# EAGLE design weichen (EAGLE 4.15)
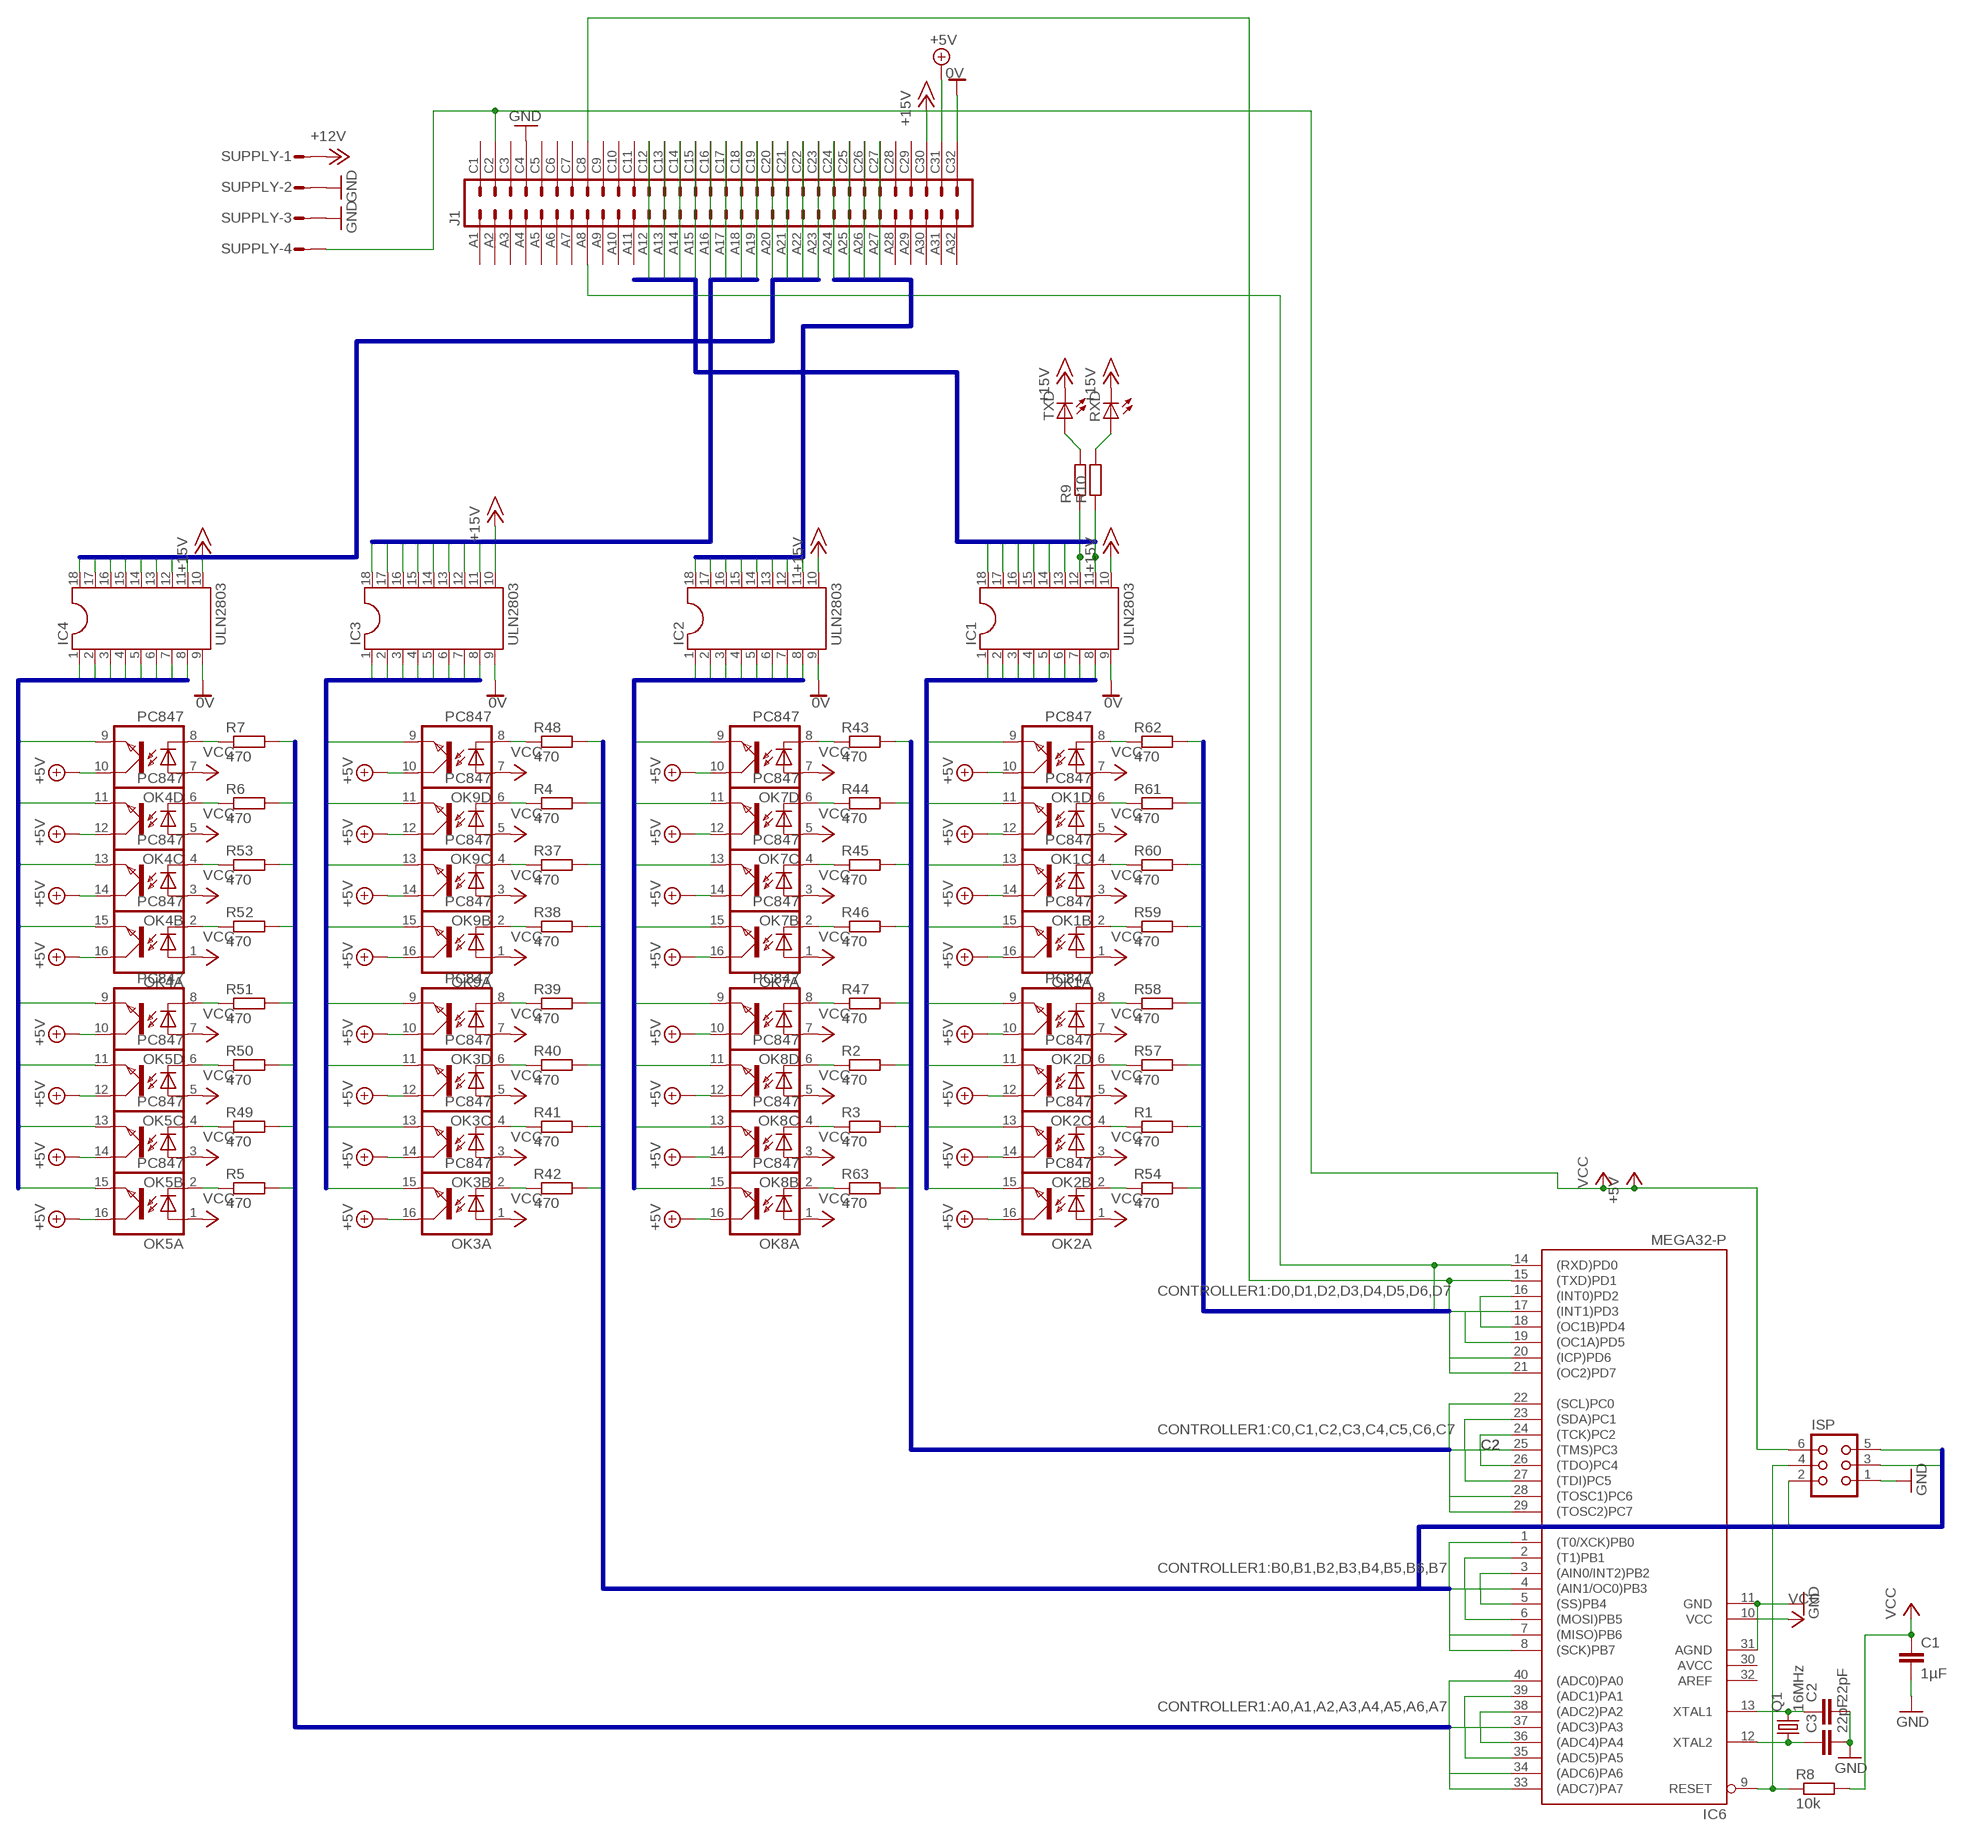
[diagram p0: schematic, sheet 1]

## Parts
C1  1µF  C-EU050-024X044  [C050-024X044]
C2  22pF  C-EU025-025X050  [C025-025X050]
C3  22pF  C-EU025-025X050  [C025-025X050]
IC1  ULN2803  DIL18  [DIL18]
IC2  ULN2803  DIL18  [DIL18]
IC3  ULN2803  DIL18  [DIL18]
IC4  ULN2803  DIL18  [DIL18]
IC6  MEGA32-P  [DIL40]
ISP  CON06L  [CON06L]
J1  VG64  [VG64]
OK1  PC847  [DIL16]
OK2  PC847  [DIL16]
OK3  PC847  [DIL16]
OK4  PC847  [DIL16]
OK5  PC847  [DIL16]
OK7  PC847  [DIL16]
OK8  PC847  [DIL16]
OK9  PC847  [DIL16]
Q1  16MHz  CRYSTALHC18U-V  [HC18U-V]
R1  470  R-EU_0204/7  [0204/7]
R2  470  R-EU_0204/7  [0204/7]
R3  470  R-EU_0204/7  [0204/7]
R4  470  R-EU_0204/7  [0204/7]
R5  470  R-EU_0204/7  [0204/7]
R6  470  R-EU_0204/7  [0204/7]
R7  470  R-EU_0204/7  [0204/7]
R8  10k  R-EU_0204/7  [0204/7]
R9  R-EU_0204/7  [0204/7]
R10  R-EU_0204/7  [0204/7]
R37  470  R-EU_0204/7  [0204/7]
R38  470  R-EU_0204/7  [0204/7]
R39  470  R-EU_0204/7  [0204/7]
R40  470  R-EU_0204/7  [0204/7]
R41  470  R-EU_0204/7  [0204/7]
R42  470  R-EU_0204/7  [0204/7]
R43  470  R-EU_0204/7  [0204/7]
R44  470  R-EU_0204/7  [0204/7]
R45  470  R-EU_0204/7  [0204/7]
R46  470  R-EU_0204/7  [0204/7]
R47  470  R-EU_0204/7  [0204/7]
R48  470  R-EU_0204/7  [0204/7]
R49  470  R-EU_0204/7  [0204/7]
R50  470  R-EU_0204/7  [0204/7]
R51  470  R-EU_0204/7  [0204/7]
R52  470  R-EU_0204/7  [0204/7]
R53  470  R-EU_0204/7  [0204/7]
R54  470  R-EU_0204/7  [0204/7]
R57  470  R-EU_0204/7  [0204/7]
R58  470  R-EU_0204/7  [0204/7]
R59  470  R-EU_0204/7  [0204/7]
R60  470  R-EU_0204/7  [0204/7]
R61  470  R-EU_0204/7  [0204/7]
R62  470  R-EU_0204/7  [0204/7]
R63  470  R-EU_0204/7  [0204/7]
RXD  LED5MM  [LED5MM]
SUPPLY  L04P  [L04P]
TXD  LED5MM  [LED5MM]

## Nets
0V: IC1.9 IC2.9 IC3.9 IC4.9 J1.C32
+5V: J1.C31 OK1.10(D:COL) OK1.12(C:COL) OK1.14(B:COL) OK1.16(A:COL) OK2.10(D:COL) OK2.12(C:COL) OK2.14(B:COL) OK2.16(A:COL) OK3.10(D:COL) OK3.12(C:COL) OK3.14(B:COL) OK3.16(A:COL) OK4.10(D:COL) OK4.12(C:COL) OK4.14(B:COL) OK4.16(A:COL) OK5.10(D:COL) OK5.12(C:COL) OK5.14(B:COL) OK5.16(A:COL) OK7.10(D:COL) OK7.12(C:COL) OK7.14(B:COL) OK7.16(A:COL) OK8.10(D:COL) OK8.12(C:COL) OK8.14(B:COL) OK8.16(A:COL) OK9.10(D:COL) OK9.12(C:COL) OK9.14(B:COL) OK9.16(A:COL)
+12V: SUPPLY.1
+15V: IC1.10 IC2.10 IC3.10 IC4.10 J1.C30 RXD.K(C) TXD.K(C)
A0: IC6.40((ADC0)PA0) R5.2
A1: IC6.39((ADC1)PA1) R49.2
A2: IC6.38((ADC2)PA2) R50.2
A3: IC6.37((ADC3)PA3) R51.2
A4: IC6.36((ADC4)PA4) R52.2
A5: IC6.35((ADC5)PA5) R53.2
A6: IC6.34((ADC6)PA6) R6.2
A7: IC6.33((ADC7)PA7) R7.2
AA0: IC4.18 J1.C20
AA1: IC4.17 J1.A20
AA2: IC4.16 J1.C21
AA3: IC4.15 J1.A21
AA4: IC4.14 J1.C22
AA5: IC4.13 J1.A22
AA6: IC4.12 J1.C23
AA7: IC4.11 J1.A23
AB0: IC3.18 J1.C16
AB1: IC3.17 J1.A16
AB2: IC3.16 J1.C17
AB3: IC3.15 J1.A17
AB4: IC3.14 J1.C18
AB5: IC3.13 J1.A18
AB6: IC3.12 J1.C19
AB7: IC3.11 J1.A19
AC0: IC2.18 J1.C24
AC1: IC2.17 J1.A24
AC2: IC2.16 J1.C25
AC3: IC2.15 J1.A25
AC4: IC2.14 J1.C26
AC5: IC2.13 J1.A26
AC6: IC2.12 J1.C27
AC7: IC2.11 J1.A27
AD0: IC1.18 J1.A12
AD1: IC1.17 J1.C12
AD2: IC1.16 J1.A13
AD3: IC1.15 J1.C13
AD4: IC1.14 J1.A14
AD5: IC1.13 J1.C14
AD6: IC1.12 J1.A15 R9.1
AD7: IC1.11 J1.C15 R10.1
B0: IC6.1((T0/XCK)PB0) R48.2
B1: IC6.2((T1)PB1) R4.2
B2: IC6.3((AIN0/INT2)PB2) R37.2
B3: IC6.4((AIN1/OC0)PB3) R38.2
B4: IC6.5((SS)PB4) R39.2
B5: IC6.6((MOSI)PB5) ISP.3 R40.2
B6: IC6.7((MISO)PB6) ISP.2 R41.2
B7: IC6.8((SCK)PB7) ISP.5 R42.2
C0: IC6.22((SCL)PC0) R43.2
C1: IC6.23((SDA)PC1) R44.2
C2: IC6.24((TCK)PC2) R45.2
C3: IC6.25((TMS)PC3) R46.2
C4: IC6.26((TDO)PC4) R47.2
C5: IC6.27((TDI)PC5) R2.2
C6: IC6.28((TOSC1)PC6) R3.2
C7: IC6.29((TOSC2)PC7) R63.2
D0: IC6.14((RXD)PD0) J1.A8 R62.2
D1: IC6.15((TXD)PD1) J1.C8 R61.2
D2: IC6.16((INT0)PD2) R60.2
D3: IC6.17((INT1)PD3) R59.2
D4: IC6.18((OC1B)PD4) R58.2
D5: IC6.19((OC1A)PD5) R57.2
D6: IC6.20((ICP)PD6) R1.2
D7: IC6.21((OC2)PD7) R54.2
GND: C1.2 C2.2 C3.2 IC6.11(GND) IC6.31(AGND) ISP.1 J1.C4 SUPPLY.2 SUPPLY.3
N$1: OK5.2(A:C) R5.1
N$2: IC6.9(RESET) ISP.4 R8.1
N$3: R10.2 RXD.A
N$4: R9.2 TXD.A
N$5: OK4.6(C:C) R6.1
N$6: OK4.8(D:C) R7.1
N$7: OK5.4(B:C) R49.1
N$8: OK5.6(C:C) R50.1
N$10: OK5.8(D:C) R51.1
N$11: OK4.2(A:C) R52.1
N$12: OK4.4(B:C) R53.1
N$13: OK9.6(C:C) R4.1
N$14: OK9.4(B:C) R37.1
N$15: OK9.2(A:C) R38.1
N$16: OK3.8(D:C) R39.1
N$17: OK3.6(C:C) R40.1
N$18: OK3.4(B:C) R41.1
N$19: OK3.2(A:C) R42.1
N$20: OK9.8(D:C) R48.1
N$21: OK8.6(C:C) R2.1
N$22: OK8.4(B:C) R3.1
N$23: OK7.8(D:C) R43.1
N$24: OK7.6(C:C) R44.1
N$25: OK7.4(B:C) R45.1
N$26: OK7.2(A:C) R46.1
N$27: OK8.8(D:C) R47.1
N$28: OK8.2(A:C) R63.1
N$29: OK2.4(B:C) R1.1
N$30: OK2.2(A:C) R54.1
N$31: OK2.6(C:C) R57.1
N$32: OK2.8(D:C) R58.1
N$33: OK1.2(A:C) R59.1
N$34: OK1.4(B:C) R60.1
N$35: OK1.6(C:C) R61.1
N$36: OK1.8(D:C) R62.1
N$41: C2.1 IC6.13(XTAL1) Q1.2
N$42: C3.1 IC6.12(XTAL2) Q1.1
OA0: IC4.8 OK4.9(D:EMIT)
OA1: IC4.7 OK4.11(C:EMIT)
OA2: IC4.6 OK4.13(B:EMIT)
OA3: IC4.5 OK4.15(A:EMIT)
OA4: IC4.4 OK5.9(D:EMIT)
OA5: IC4.3 OK5.11(C:EMIT)
OA6: IC4.2 OK5.13(B:EMIT)
OA7: IC4.1 OK5.15(A:EMIT)
OB0: IC3.8 OK9.9(D:EMIT)
OB1: IC3.7 OK9.11(C:EMIT)
OB2: IC3.6 OK9.13(B:EMIT)
OB3: IC3.5 OK9.15(A:EMIT)
OB4: IC3.4 OK3.9(D:EMIT)
OB5: IC3.3 OK3.11(C:EMIT)
OB6: IC3.2 OK3.13(B:EMIT)
OB7: IC3.1 OK3.15(A:EMIT)
OC0: IC2.8 OK7.9(D:EMIT)
OC1: IC2.7 OK7.11(C:EMIT)
OC2: IC2.6 OK7.13(B:EMIT)
OC3: IC2.5 OK7.15(A:EMIT)
OC4: IC2.4 OK8.9(D:EMIT)
OC5: IC2.3 OK8.11(C:EMIT)
OC6: IC2.2 OK8.13(B:EMIT)
OC7: IC2.1 OK8.15(A:EMIT)
OD0: IC1.8 OK1.9(D:EMIT)
OD1: IC1.7 OK1.11(C:EMIT)
OD2: IC1.6 OK1.13(B:EMIT)
OD3: IC1.5 OK1.15(A:EMIT)
OD4: IC1.4 OK2.9(D:EMIT)
OD5: IC1.3 OK2.11(C:EMIT)
OD6: IC1.2 OK2.13(B:EMIT)
OD7: IC1.1 OK2.15(A:EMIT)
VCC: C1.1 IC6.10(VCC) ISP.6 J1.C2 OK1.1(A:A) OK1.3(B:A) OK1.5(C:A) OK1.7(D:A) OK2.1(A:A) OK2.3(B:A) OK2.5(C:A) OK2.7(D:A) OK3.1(A:A) OK3.3(B:A) OK3.5(C:A) OK3.7(D:A) OK4.1(A:A) OK4.3(B:A) OK4.5(C:A) OK4.7(D:A) OK5.1(A:A) OK5.3(B:A) OK5.5(C:A) OK5.7(D:A) OK7.1(A:A) OK7.3(B:A) OK7.5(C:A) OK7.7(D:A) OK8.1(A:A) OK8.3(B:A) OK8.5(C:A) OK8.7(D:A) OK9.1(A:A) OK9.3(B:A) OK9.5(C:A) OK9.7(D:A) R8.2 SUPPLY.4 ; supply symbol labelled +5V
Unconnected: J1.A1 J1.A2 J1.A3 J1.A4 J1.A5 J1.A6 J1.A7 J1.A9 J1.A10 J1.A11 J1.A28 J1.A29 J1.A30 J1.A31 J1.A32 J1.C1 J1.C3 J1.C5 J1.C6 J1.C7 J1.C9 J1.C10 J1.C11 J1.C28 J1.C29

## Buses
CONTROLLER1:A0,A1,A2,A3,A4,A5,A6,A7
CONTROLLER1:B0,B1,B2,B3,B4,B5,B6,B7
CONTROLLER1:C0,C1,C2,C3,C4,C5,C6,C7
CONTROLLER1:D0,D1,D2,D3,D4,D5,D6,D7
OPTOKOPPLER1:OD0,OD1,OD2,OD3,OD4,OD5,OD6,OD7
OPTOKOPPLER1:OC0,OC1,OC2,OC3,OC4,OC5,OC6,OC7
OPTOKOPPLER1:OB0,OB1,OB2,OB3,OB4,OB5,OB6,OB7
OPTOKOPPLER1:OA0,OA1,OA2,OA3,OA4,OA5,OA6,OA7
AUSGANG:AD0,AD1,AD2,AD3,AD4,AD5,AD6,AD7
AUSGANG:AC0,AC1,AC2,AC3,AC4,AC5,AC6,AC7
AUSGANG:AA0,AA1,AA2,AA3,AA4,AA5,AA6,AA7
AUSGANG:AB0,AB1,AB2,AB3,AB4,AB5,AB6,AB7

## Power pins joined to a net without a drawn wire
AREF: IC6.32(AREF)
AVCC: IC6.30(AVCC)

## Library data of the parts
C1-C3 = rcl:C-EU: CAPACITOR, European symbol
IC1-IC4 = ic-package:DIL18: Dual In Line
IC6 = atmel:MEGA32-P: MICROCONTROLLER 32 Kbytes FLASH 2 Kbytes SRAM 1 Kbytes EEPROM USART 8-channel 10 bit ADC Source: www.atmel.com .. doc2503.pdf
ISP = con-harting:CON06L: CONNECTOR
J1 = 19inch:VG64: PCB EUROCARD, 64-pin type C/AC, 2.54 mm
OK1-OK5 OK7-OK9 = optocoupler:PC847: SHARP OPTO COUPLER
Q1 = crystal:CRYSTAL: CRYSTAL
R1-R10 R37-R54 R57-R63 = rcl:R-EU_: RESISTOR, European symbol
RXD TXD = led:LED: LED
SUPPLY = con-amp-mt:L04P: AMP MT CONNECTOR

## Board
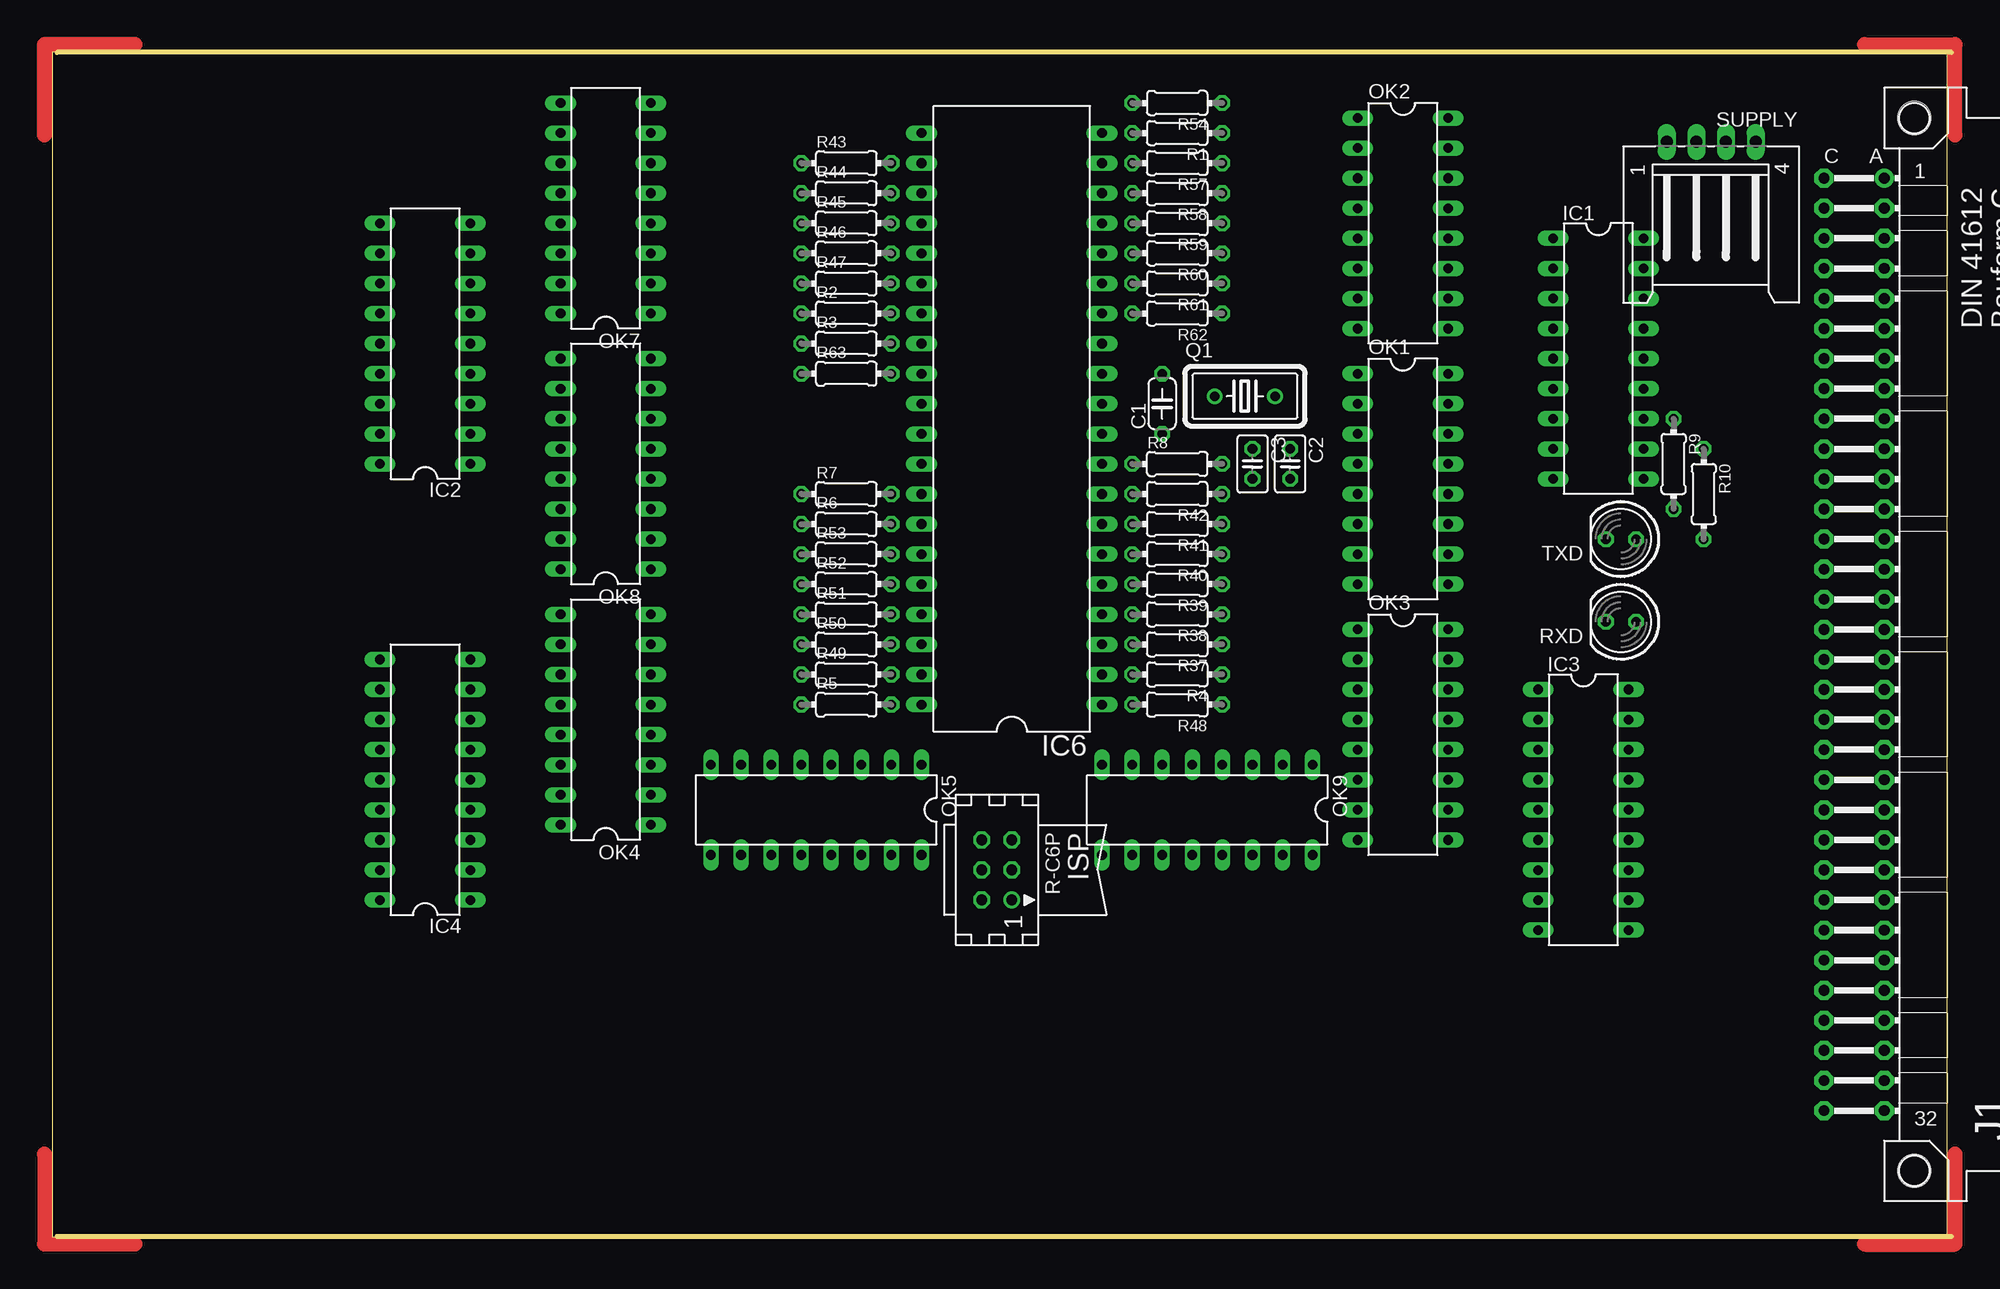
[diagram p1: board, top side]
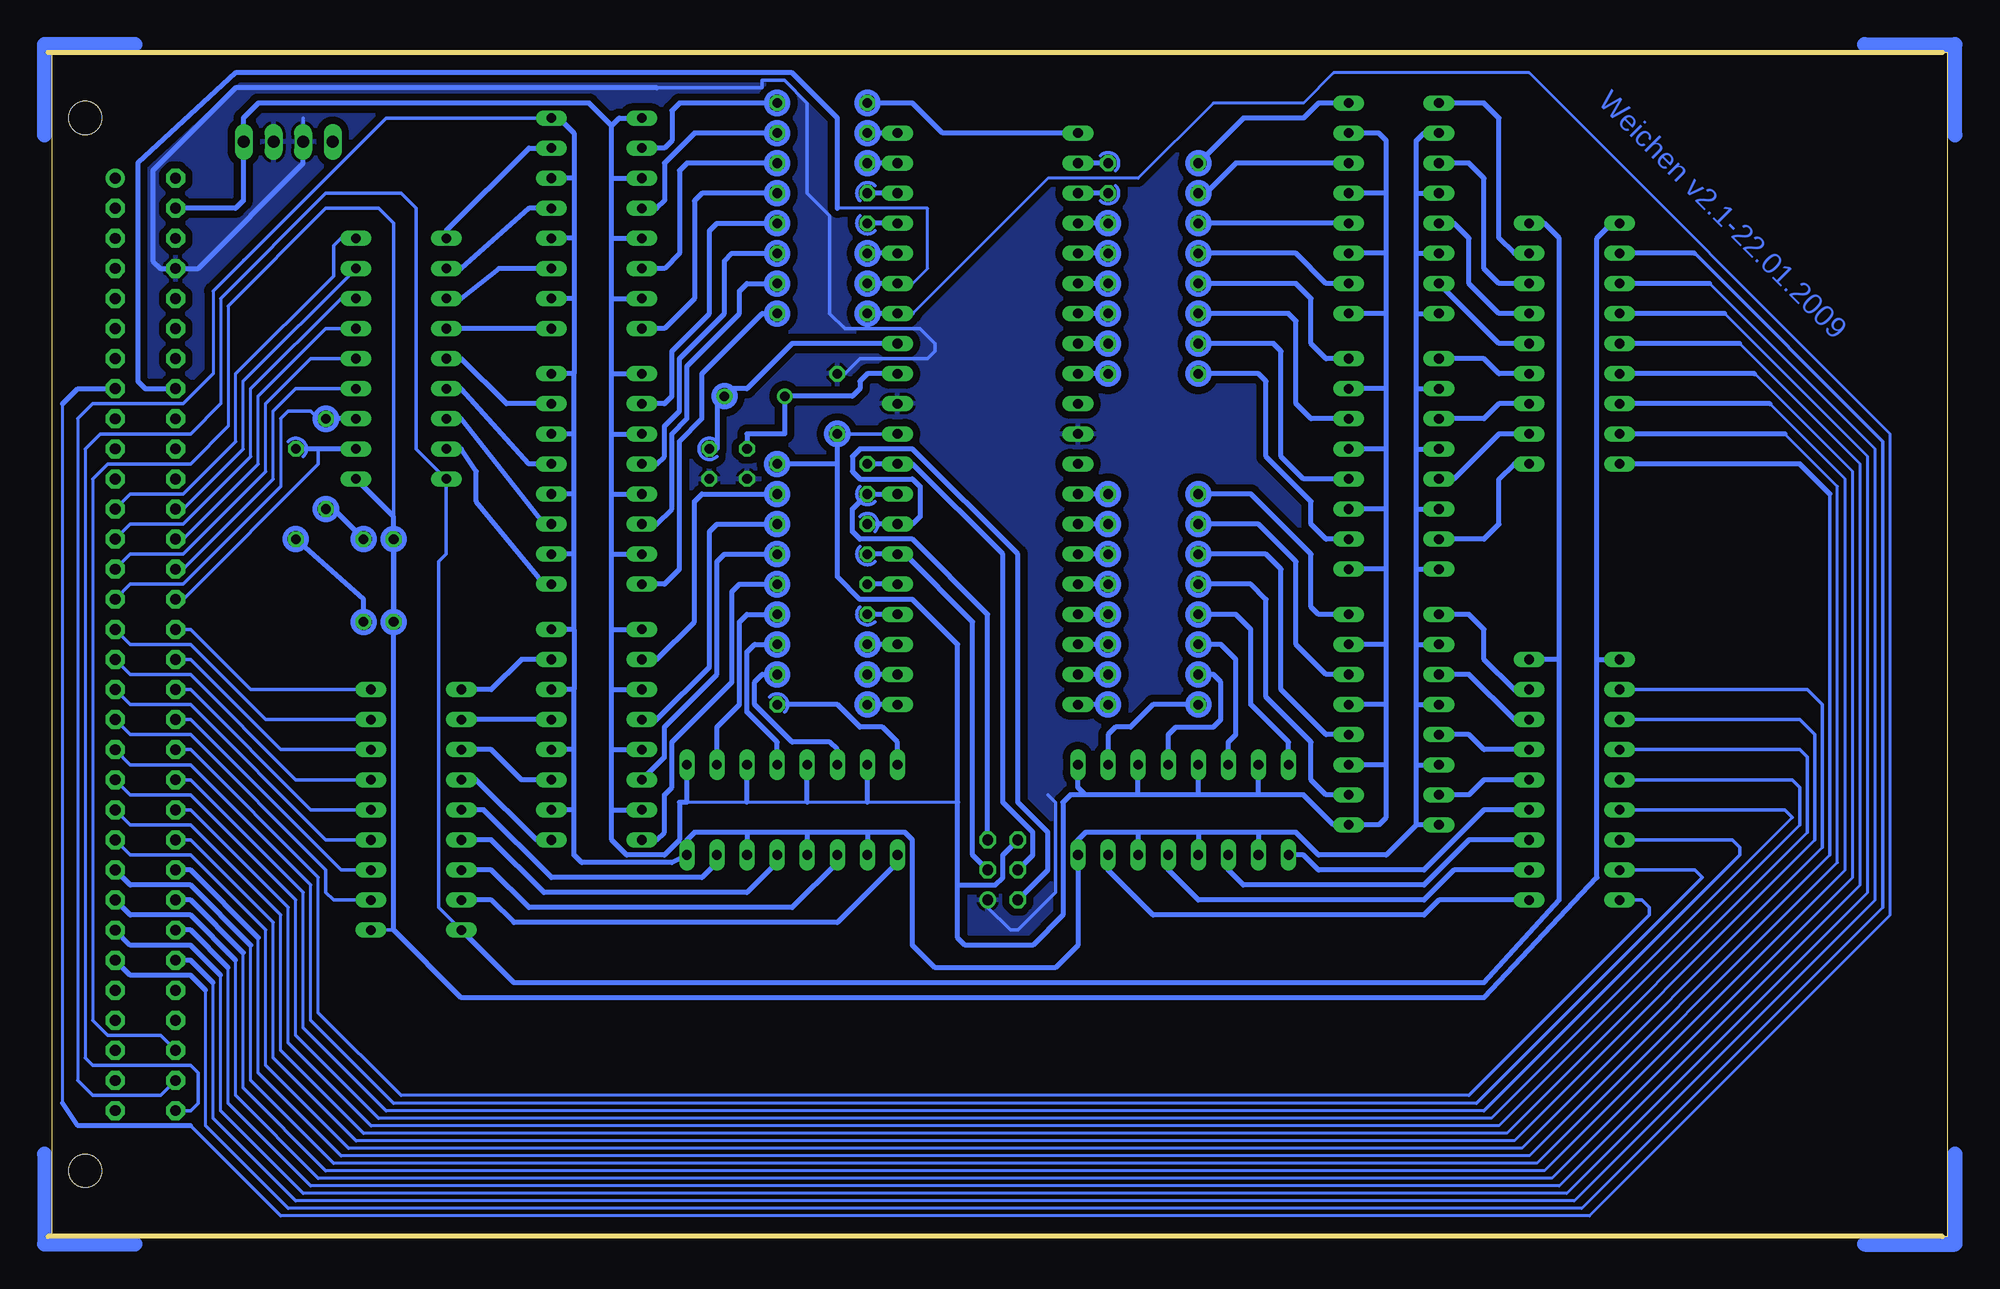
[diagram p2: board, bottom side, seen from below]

Size 160.39 x 100.03 mm. Coordinates in mm from the lower left corner, seen from the top.
Outline: 0.39,0.01 160.39,0.01
Outline: 160.39,100.01 0.39,100.01
Copper layers (1*16): Top 0.035mm / dielectric 1.5mm / Bottom 0.035mm
Design rules "default": minimum track width 10mil, minimum drill 24mil, track to track 8mil, track to pad 8mil, pad to pad 8mil, via to via 8mil, smd to smd 8mil, copper to edge 40mil, drill to drill 8mil, minimum pad ring 10mil, minimum via ring 8mil, stop-mask expansion 4mil, vias tented up to drill 0mil, thermal gap 10mil

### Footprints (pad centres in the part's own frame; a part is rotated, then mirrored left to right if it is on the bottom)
C050-024X044 = drill 0.813 octagon: 1 -2.54,0; 2 2.54,0
C025-025X050 = drill 0.813 octagon: 1 -1.27,0; 2 1.27,0
DIL18 = drill 0.813 long: 1 -10.16,-3.81; 2 -7.62,-3.81; 3 -5.08,-3.81; 4 -2.54,-3.81; 5 0,-3.81; 6 2.54,-3.81; 7 5.08,-3.81; 8 7.62,-3.81; 9 10.16,-3.81; 10 10.16,3.81; 11 7.62,3.81; 12 5.08,3.81; 13 2.54,3.81; 14 0,3.81; 15 -2.54,3.81; 16 -5.08,3.81; 17 -7.62,3.81; 18 -10.16,3.81
DIL40 = drill 0.813 long: 1 -24.13,-7.62; 2 -21.59,-7.62; 3 -19.05,-7.62; 4 -16.51,-7.62; 5 -13.97,-7.62; 6 -11.43,-7.62; 7 -8.89,-7.62; 8 -6.35,-7.62; 9 -3.81,-7.62; 10 -1.27,-7.62; 11 1.27,-7.62; 12 3.81,-7.62; 13 6.35,-7.62; 14 8.89,-7.62; 15 11.43,-7.62; 16 13.97,-7.62; 17 16.51,-7.62; 18 19.05,-7.62; 19 21.59,-7.62; 20 24.13,-7.62; 21 24.13,7.62; 22 21.59,7.62; 23 19.05,7.62; 24 16.51,7.62; 25 13.97,7.62; 26 11.43,7.62; 27 8.89,7.62; 28 6.35,7.62; 29 3.81,7.62; 30 1.27,7.62; 31 -1.27,7.62; 32 -3.81,7.62; 33 -6.35,7.62; 34 -8.89,7.62; 35 -11.43,7.62; 36 -13.97,7.62; 37 -16.51,7.62; 38 -19.05,7.62; 39 -21.59,7.62; 40 -24.13,7.62
CON06L = drill 0.914 round: 1 2.54,1.27 | drill 0.914 octagon: 2 2.54,-1.27; 3 0,1.27; 4 0,-1.27; 5 -2.54,1.27; 6 -2.54,-1.27
VG64 = drill 0.914 pad 1.6 round: A1 154.94,39.37 | drill 0.914 pad 1.6 octagon: A2 154.94,36.83; A3 154.94,34.29; A4 154.94,31.75; A5 154.94,29.21; A6 154.94,26.67; A7 154.94,24.13; A8 154.94,21.59; A9 154.94,19.05; A10 154.94,16.51; A11 154.94,13.97; A12 154.94,11.43; A13 154.94,8.89; A14 154.94,6.35; A15 154.94,3.81; A16 154.94,1.27; A17 154.94,-1.27; A18 154.94,-3.81; A19 154.94,-6.35; A20 154.94,-8.89; A21 154.94,-11.43; A22 154.94,-13.97; A23 154.94,-16.51; A24 154.94,-19.05; A25 154.94,-21.59; A26 154.94,-24.13; A27 154.94,-26.67; A28 154.94,-29.21; A29 154.94,-31.75; A30 154.94,-34.29; A31 154.94,-36.83; A32 154.94,-39.37; C1 149.86,39.37; C2 149.86,36.83; C3 149.86,34.29; C4 149.86,31.75; C5 149.86,29.21; C6 149.86,26.67; C7 149.86,24.13; C8 149.86,21.59; C9 149.86,19.05; C10 149.86,16.51; C11 149.86,13.97; C12 149.86,11.43; C13 149.86,8.89; C14 149.86,6.35; C15 149.86,3.81; C16 149.86,1.27; C17 149.86,-1.27; C18 149.86,-3.81; C19 149.86,-6.35; C20 149.86,-8.89; C21 149.86,-11.43; C22 149.86,-13.97; C23 149.86,-16.51; C24 149.86,-19.05; C25 149.86,-21.59; C26 149.86,-24.13; C27 149.86,-26.67; C28 149.86,-29.21; C29 149.86,-31.75; C30 149.86,-34.29; C31 149.86,-36.83; C32 149.86,-39.37 | hole 2.794: 157.48,44.45; 157.48,-44.45
DIL16 = drill 0.813 long: 1 -8.89,-3.81; 2 -6.35,-3.81; 3 -3.81,-3.81; 4 -1.27,-3.81; 5 1.27,-3.81; 6 3.81,-3.81; 7 6.35,-3.81; 8 8.89,-3.81; 9 8.89,3.81; 10 6.35,3.81; 11 3.81,3.81; 12 1.27,3.81; 13 -1.27,3.81; 14 -3.81,3.81; 15 -6.35,3.81; 16 -8.89,3.81
HC18U-V = drill 0.813 round: 1 -2.54,0; 2 2.54,0
0204/7 = drill 0.813 octagon: 1 -3.81,0; 2 3.81,0
LED5MM = drill 0.813 octagon: A -1.27,0; K 1.27,0
L04P = drill 1.016 long: 1 3.75,-6.25; 2 1.25,-6.25; 3 -1.25,-6.25; 4 -3.75,-6.25

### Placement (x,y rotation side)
C1  93.73,70.33 90 top
C2  104.52,65.25 270 top
C3  101.35,65.25 270 top
IC1  130.56,74.14 270 top
IC2  31.5,75.41 90 top
IC3  129.29,36.04 270 top
IC4  31.5,38.58 90 top
IC6  81.03,69.06 90 top
ISP  79.76,30.96 270 top
J1  -0.25,50.01 0 top
OK1  114.05,63.98 270 top
OK2  114.05,85.57 270 top
OK3  114.05,42.39 270 top
OK4  46.74,43.66 90 top
OK5  64.52,36.04 180 top
OK7  46.74,86.84 90 top
OK8  46.74,65.25 90 top
OK9  97.54,36.04 180 top
Q1  100.71,70.97 0 top
R1  95,93.19 180 top
R2  67.06,77.95 0 top
R3  67.06,75.41 0 top
R4  95,47.47 180 top
R5  67.06,44.93 0 top
R6  67.06,60.17 0 top
R7  67.06,62.71 0 top
R8  95,65.25 0 top
R9  136.91,65.25 270 top
R10  139.45,62.71 270 top
R37  95,50.01 180 top
R38  95,52.55 180 top
R39  95,55.09 180 top
R40  95,57.63 180 top
R41  95,60.17 180 top
R42  95,62.71 180 top
R43  67.06,90.65 0 top
R44  67.06,88.11 0 top
R45  67.06,85.57 0 top
R46  67.06,83.03 0 top
R47  67.06,80.49 0 top
R48  95,44.93 180 top
R49  67.06,47.47 0 top
R50  67.06,50.01 0 top
R51  67.06,52.55 0 top
R52  67.06,55.09 0 top
R53  67.06,57.63 0 top
R54  95,95.73 180 top
R57  95,90.65 180 top
R58  95,88.11 180 top
R59  95,85.57 180 top
R60  95,83.03 180 top
R61  95,80.49 180 top
R62  95,77.95 180 top
R63  67.06,72.87 0 top
RXD  132.46,51.92 180 top
SUPPLY  140.08,86.21 180 top
TXD  132.46,58.9 180 top

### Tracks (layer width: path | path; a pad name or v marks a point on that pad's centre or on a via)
0V
  Bottom 0.254: 145.8,79.22 145.8,70.33 | 157.23,66.52 157.23,15.09
  Bottom 0.305: IC3.9 127.38,27.79 127.38,57 126.75,57.63 IC1.9 129.29,66.52 129.29,86.84 130.56,88.11 136.91,88.11 145.8,79.22 | 145.8,70.33 148.34,67.79 155.96,67.79 157.23,66.52 | 157.23,15.09 156.59,14.45 148.34,14.45 147.7,13.82 147.7,11.28 148.34,10.64 J1.C32
  Bottom 0.406: 32.77,48.74 32.77,84.3 34.04,85.57 IC2.9 | 32.77,48.74 IC4.9 | 32.77,48.74 32.77,28.42 39.12,21.44 121.03,21.44 IC3.9
+5V
  Bottom 0.254: 146.43,79.86 146.43,72.87 | 157.86,69.06 157.86,13.18
  Bottom 0.305: 115.95,36.04 115.95,51.28 115.95,93.19 | 117.22,94.46 118.49,94.46 131.83,94.46 143.89,82.4 | 143.89,82.4 146.43,79.86 | 146.43,72.87 148.97,70.33 156.59,70.33 157.86,69.06 | 157.86,13.18 156.59,11.91 150.88,11.91 J1.C31 | 143.89,82.4 143.83,82.46
  Bottom 0.406: 101.35,34.14 OK9.14 | 96.27,34.14 101.35,34.14 | 96.27,34.14 OK9.12 | 91.19,34.14 96.27,34.14 | 115.95,36.04 OK3.10 | 115.95,89.38 115.95,84.3 | 115.95,84.3 OK2.12 | 115.95,84.3 115.95,79.22 | 115.95,79.22 OK2.10 | 115.95,79.22 115.95,72.87 | 115.95,72.87 OK1.16 | 115.95,67.79 115.95,72.87 | 115.95,67.79 OK1.14 | 115.95,62.71 115.95,67.79 | 115.95,62.71 OK1.12 | 115.95,57.63 115.95,62.71 | 115.95,51.28 115.95,46.2 | 115.95,46.2 OK3.14 | 115.95,41.12 115.95,46.2 | 115.95,41.12 OK3.12 | 115.95,36.04 115.95,41.12 | 115.95,89.38 OK2.14 | 115.95,89.38 115.95,93.19 117.22,94.46 OK2.16 118.49,94.46 | 68.33,34.14 72.77,34.14 73.41,33.5 OK5.16 73.41,24.61 75.31,22.71 85.47,22.71 87.38,24.61 87.38,33.5 88.01,34.14 91.19,34.14 | 68.33,34.14 OK5.14 | 63.25,34.14 68.33,34.14 | 63.25,34.14 OK5.12 | 58.17,34.14 63.25,34.14 | 44.83,34.77 47.37,32.23 53.09,32.23 54.99,34.14 58.17,34.14 | OK4.16 44.83,34.77 | 44.83,34.77 44.83,39.85 | 44.83,39.85 OK4.14 | 44.83,39.85 44.83,44.93 | 44.83,44.93 OK4.12 | 44.83,44.93 44.83,50.01 | 44.83,50.01 OK4.10 | 44.83,50.01 44.83,56.36 | 44.83,56.36 OK8.16 | 44.83,56.36 44.83,61.44 | 44.83,61.44 OK8.14 | 44.83,61.44 44.83,66.52 | 44.83,66.52 OK8.12 | 44.83,66.52 44.83,71.6 | 44.83,71.6 OK8.10 | 44.83,71.6 44.83,77.95 | 44.83,77.95 OK7.16 | 44.83,77.95 44.83,83.03 | 44.83,83.03 OK7.14 | 44.83,83.03 44.83,88.11 | 44.83,88.11 OK7.12 | 44.83,88.11 44.83,92.56 44.2,93.19 OK7.10 | 58.17,34.14 OK5.10 | 91.19,34.14 OK9.10 | 101.35,34.14 105.79,34.14 106.43,33.5 OK9.16 107.7,31.6 115.32,31.6 115.95,32.23 115.95,36.04 | 115.95,57.63 OK1.10 | 115.95,51.28 115.95,57.63 | 115.95,51.28 OK3.16
+15V
  Bottom 0.254: 145.16,78.59 145.16,68.43 | 156.59,63.98 156.59,18.26
  Bottom 0.305: TXD.K 131.19,85.57 132.46,86.84 136.91,86.84 145.16,78.59 | 145.16,68.43 148.34,65.25 155.32,65.25 156.59,63.98 | 156.59,18.26 155.32,16.99 150.88,16.99 J1.C30 | 131.19,25.88 IC3.10
  Bottom 0.406: IC1.10 131.19,60.81 TXD.K | 29.59,48.74 IC4.10 | IC2.10 28.32,85.57 29.59,84.3 29.59,48.74 | 29.59,48.74 29.59,30.33 39.12,20.17 125.48,20.17 131.19,25.88 TXD.K | TXD.K RXD.K
A0
  Bottom 0.406: R5.2 IC6.40
A1
  Bottom 0.406: R49.2 IC6.39
A2
  Bottom 0.406: R50.2 IC6.38
A3
  Bottom 0.406: R51.2 IC6.37
A4
  Bottom 0.406: R52.2 IC6.36
A5
  Bottom 0.406: R53.2 IC6.35
A6
  Bottom 0.406: R6.2 IC6.34
A7
  Bottom 0.406: R7.2 IC6.33
AA0
  Bottom 0.254: 40.39,11.91 130.56,11.91 | 137.54,18.9 137.54,30.33
  Bottom 0.305: IC4.18 25.78,28.42 25.15,27.79 25.15,27.15 40.39,11.91 | 130.56,11.91 137.54,18.9 | J1.C20 148.34,41.12 137.54,30.33
AA1
  Bottom 0.254: 39.75,11.28 131.19,11.28 | 138.18,18.26 138.18,29.69
  Bottom 0.305: IC4.17 21.34,30.96 20.7,30.33 39.75,11.28 | 131.19,11.28 138.18,18.26 | 138.18,29.69 148.34,39.85 153.42,39.85 J1.A20
AA2
  Bottom 0.254: 39.12,10.64 131.83,10.64 | 138.81,17.63 138.81,29.06
  Bottom 0.305: IC4.16 18.16,33.5 17.53,32.87 17.53,32.23 39.12,10.64 | 131.83,10.64 138.81,17.63 | 138.81,29.06 148.34,38.58 J1.C21
AA3
  Bottom 0.254: 13.08,35.41 38.48,10.01 132.46,10.01 | 139.45,16.99 139.45,28.42
  Bottom 0.305: IC4.15 13.72,36.04 13.08,35.41 | 132.46,10.01 139.45,16.99 | 139.45,28.42 148.34,37.31 153.42,37.31 J1.A21
AA4
  Bottom 0.254: 12.45,34.77 37.85,9.37 133.1,9.37 | 140.08,16.36 140.08,27.79
  Bottom 0.305: IC4.14 13.08,38.58 12.45,37.95 12.45,34.77 | 133.1,9.37 140.08,16.36 | 140.08,27.79 148.34,36.04 J1.C22
AA5
  Bottom 0.254: 11.81,34.14 37.21,8.74 133.73,8.74 | 140.72,15.72 140.72,27.15
  Bottom 0.305: 27.05,41.12 12.45,41.12 11.81,40.49 11.81,34.14 | 133.73,8.74 140.72,15.72 | 140.72,27.15 148.34,34.77 153.42,34.77 J1.A22
  Bottom 0.406: 27.05,41.12 IC4.13
AA6
  Bottom 0.254: 11.18,33.5 36.58,8.1 134.37,8.1 | 141.35,15.09 141.35,26.52
  Bottom 0.305: IC4.12 12.45,43.66 11.18,42.39 11.18,33.5 | 134.37,8.1 141.35,15.09 | 141.35,26.52 148.34,33.5 J1.C23
AA7
  Bottom 0.254: 10.54,32.87 35.94,7.47 135,7.47 | 141.99,14.45 141.99,25.88
  Bottom 0.305: 27.05,46.2 11.81,46.2 10.54,44.93 10.54,32.87 | 135,7.47 141.99,14.45 | 141.99,25.88 148.34,32.23 153.42,32.23 J1.A23
  Bottom 0.406: 27.05,46.2 IC4.11
AB0
  Bottom 0.305: IC3.18 143.26,46.2 148.34,51.28 J1.C16
AB1
  Bottom 0.305: IC3.17 141.99,43.66 148.34,50.01 153.42,50.01 J1.A16
AB2
  Bottom 0.305: IC3.16 140.72,41.12 148.34,48.74 J1.C17
AB3
  Bottom 0.305: IC3.15 139.45,38.58 148.34,47.47 153.42,47.47 J1.A17
AB4
  Bottom 0.305: IC3.14 138.18,36.04 148.34,46.2 J1.C18
AB5
  Bottom 0.305: IC3.13 136.91,33.5 148.34,44.93 153.42,44.93 J1.A18
AB6
  Bottom 0.305: IC3.12 135.64,30.96 148.34,43.66 J1.C19
AB7
  Bottom 0.305: IC3.11 136.27,28.42 136.91,29.06 136.91,30.96 148.34,42.39 153.42,42.39 J1.A19
AC0
  Bottom 0.254: 9.91,32.23 35.31,6.83 135.64,6.83 | 142.62,13.82 142.62,25.25
  Bottom 0.305: 9.91,32.23 9.91,62.71 | 135.64,6.83 142.62,13.82
  Bottom 0.406: IC2.18 12.45,65.25 9.91,62.71 | 142.62,25.25 148.34,30.96 J1.C24
AC1
  Bottom 0.254: 13.72,67.79 9.27,63.35 9.27,31.6 34.67,6.2 136.27,6.2 | 143.26,13.18 143.26,24.61
  Bottom 0.305: 136.27,6.2 143.26,13.18
  Bottom 0.406: 13.72,67.79 IC2.17 | 143.26,24.61 148.34,29.69 153.42,29.69 J1.A24
AC2
  Bottom 0.254: 14.99,70.33 8.64,63.98 8.64,30.96 34.04,5.56 136.91,5.56 | 143.89,12.55 143.89,23.98
  Bottom 0.305: 136.91,5.56 143.89,12.55
  Bottom 0.406: 14.99,70.33 IC2.16 | 143.89,23.98 148.34,28.42 J1.C25
AC3
  Bottom 0.254: 16.26,72.87 8,64.62 8,30.33 33.4,4.93 137.54,4.93 | 144.53,11.91 144.53,23.34
  Bottom 0.305: 137.54,4.93 144.53,11.91
  Bottom 0.406: 16.26,72.87 IC2.15 | 144.53,23.34 148.34,27.15 153.42,27.15 J1.A25
AC4
  Bottom 0.254: 17.53,75.41 7.37,65.25 7.37,29.69 32.77,4.29 138.18,4.29 | 145.16,11.28 145.16,22.71
  Bottom 0.305: 138.18,4.29 145.16,11.28
  Bottom 0.406: 17.53,75.41 IC2.14 | 145.16,22.71 148.34,25.88 J1.C26
AC5
  Bottom 0.254: 18.8,77.95 6.73,65.89 6.73,29.06 32.13,3.66 138.81,3.66 | 145.8,10.64 145.8,22.07
  Bottom 0.305: 138.81,3.66 145.8,10.64
  Bottom 0.406: 18.8,77.95 IC2.13 | 145.8,22.07 148.34,24.61 153.42,24.61 J1.A26
AC6
  Bottom 0.254: 20.07,80.49 6.1,66.52 6.1,28.42 31.5,3.02 139.45,3.02 | 146.43,10.01 146.43,21.44
  Bottom 0.305: 139.45,3.02 146.43,10.01
  Bottom 0.406: 20.07,80.49 IC2.12 | 146.43,21.44 148.34,23.34 J1.C27
AC7
  Bottom 0.254: 5.46,27.79 30.86,2.39 140.08,2.39 | 147.07,9.37 147.07,20.8
  Bottom 0.305: 21.34,83.03 5.46,67.16 5.46,27.79 | 140.08,2.39 147.07,9.37
  Bottom 0.406: 21.34,83.03 IC2.11 | 147.07,20.8 148.34,22.07 153.42,22.07 J1.A27
AD0
  Bottom 0.254: 144.53,67.16 144.53,72.87
  Bottom 0.305: IC1.18 135.64,84.3 136.27,83.67 136.27,81.13 144.53,72.87 | 144.53,67.16 148.97,62.71 153.42,62.71 J1.A12
AD1
  Bottom 0.254: 143.89,66.52 143.89,72.24
  Bottom 0.305: 143.89,72.24 IC1.17 | 143.89,66.52 148.97,61.44 J1.C12
AD2
  Bottom 0.254: 143.26,65.89 143.26,71.6
  Bottom 0.305: IC1.16 135.64,79.22 143.26,71.6 | 143.26,65.89 148.97,60.17 153.42,60.17 J1.A13
AD3
  Bottom 0.254: 142.62,65.25 142.62,70.97
  Bottom 0.305: IC1.15 136.91,76.68 142.62,70.97 | 142.62,65.25 148.97,58.9 J1.C13
AD4
  Bottom 0.254: 141.99,64.62 141.99,70.33
  Bottom 0.305: IC1.14 138.18,74.14 141.99,70.33 | 141.99,64.62 148.97,57.63 153.42,57.63 J1.A14
AD5
  Bottom 0.254: 141.35,63.98 141.35,69.7
  Bottom 0.305: IC1.13 139.45,71.6 141.35,69.7 | 141.35,63.98 148.97,56.36 J1.C14
AD6
  Bottom 0.254: 140.72,69.06 140.72,63.35
  Bottom 0.305: R9.1 137.54,69.06 138.18,69.7 140.08,69.7 140.72,69.06 | 140.72,63.35 148.97,55.09 153.42,55.09 J1.A15
  Bottom 0.406: IC1.12 R9.1
AD7
  Bottom 0.305: 137.54,66.52 137.54,65.25 148.97,53.82 J1.C15
  Bottom 0.406: IC1.11 137.54,66.52 R10.1
B0
  Bottom 0.406: IC6.1 R48.2
B1
  Bottom 0.406: IC6.2 R4.2
B2
  Bottom 0.406: IC6.3 R37.2
B3
  Bottom 0.406: IC6.4 R38.2
B4
  Bottom 0.406: IC6.5 R39.2
B5
  Bottom 0.406: 88.01,57.63 IC6.6 | 88.01,57.63 R40.2 | 88.01,57.63 82.3,51.92 82.3,32.23 ISP.3
B6
  Bottom 0.406: 87.38,60.17 IC6.7 | 87.38,60.17 R41.2 | 87.38,60.17 86.74,60.81 86.74,63.35 87.38,63.98 91.82,63.98 92.46,64.62 92.46,65.89 91.82,66.52 87.38,66.52 78.49,57.63 78.49,36.68 75.95,34.14 75.95,30.96 ISP.2
B7
  Bottom 0.406: IC6.8 R42.2 92.46,61.44 92.46,59.54 91.82,58.9 87.38,58.9 81.03,52.55 ISP.5
C0
  Bottom 0.406: R43.2 IC6.22
C1
  Bottom 0.406: R44.2 IC6.23
C2
  Bottom 0.406: R45.2 IC6.24
C3
  Bottom 0.406: R46.2 IC6.25
C4
  Bottom 0.406: R47.2 IC6.26
C5
  Bottom 0.406: R2.2 IC6.27
C6
  Bottom 0.406: R3.2 IC6.28
C7
  Bottom 0.406: R63.2 IC6.29
D0
  Bottom 0.254: 140.72,1.75 30.23,1.75 4.83,27.15 4.83,67.79 35.31,98.27 51.82,98.27 54.36,95.73 61.98,95.73 68.33,89.38 75.95,89.38 87.38,77.95 | 159.13,11.28 159.13,70.33
  Bottom 0.305: 140.72,1.75 148.34,9.37
  Bottom 0.406: IC6.14 87.38,77.95 R62.2 | 148.34,9.37 157.86,9.37 159.13,11.28 | 159.13,70.33 157.86,71.6 J1.A8
D1
  Bottom 0.254: 93.73,86.84 86.11,86.84 86.11,81.76 87.38,80.49 IC6.15
  Bottom 0.406: IC6.15 R61.2 | J1.C8 152.15,71.6 152.78,72.24 152.78,90.65 144.53,98.27 97.54,98.27 93.73,94.46 93.73,86.84
D2
  Bottom 0.406: IC6.16 R60.2
D3
  Bottom 0.406: IC6.17 R59.2
D4
  Bottom 0.406: IC6.18 R58.2
D5
  Bottom 0.406: IC6.19 R57.2
D6
  Bottom 0.406: IC6.20 R1.2
D7
  Bottom 0.406: IC6.21 84.84,93.19 87.38,95.73 R54.2
GND
  Bottom 0.305: 91.82,74.14 86.74,74.14 | J1.C4 147.7,81.76 146.43,83.03 | SUPPLY.2 138.83,92.54 138.81,92.56 138.81,94.46 | C1.2 93.09,72.87 91.82,74.14 | 91.82,74.14 86.11,74.14 85.47,74.78 85.47,75.41 86.74,76.68 93.09,76.68 94.36,77.95 94.36,86.21 96.27,88.11 96.27,95.73 98.17,97.64 100.08,97.64 100.08,97 108.97,97 | ISP.1 81.03,27.79 79.12,25.88 78.49,25.88 75.31,29.06 75.31,36.68 75.95,37.31
  Bottom 0.406: SUPPLY.2 138.83,90.63 147.7,81.76 150.88,81.76 151.51,82.4 151.51,90.02 144.53,97 108.97,97
  pour Bottom (isolate 0.61): 0.38,99.54 0.38,0.48 159.77,0.48 159.77,99.54
N$1
  Bottom 0.406: R5.1 67.06,44.93 68.96,43.03 70.23,43.03 70.87,42.39 OK5.2
N$2
  Bottom 0.406: R8.1 IC6.9 87.38,65.25 79.76,57.63 79.76,36.68 77.22,34.14 77.22,32.23 ISP.4
N$3
  Bottom 0.406: R10.2 133.73,53.82 RXD.A
N$4
  Bottom 0.406: TXD.A 136.27,61.44 R9.2
N$5
  Bottom 0.406: R6.1 58.17,60.17 54.99,57 54.99,50.01 52.45,47.47 OK4.6
N$6
  Bottom 0.406: R7.1 58.8,62.71 53.72,57.63 53.72,53.19 53.09,52.55 OK4.8
N$7
  Bottom 0.406: R49.1 61.98,47.47 61.34,46.84 61.34,43.66 61.98,43.03 65.15,43.03 65.79,42.39 OK5.4
N$8
  Bottom 0.406: R50.1 61.34,50.01 60.07,48.74 60.07,42.39 60.71,41.76 OK5.6
N$10
  Bottom 0.406: R51.1 60.07,52.55 58.8,51.28 58.8,44.93 55.63,41.76 OK5.8
N$11
  Bottom 0.406: R52.1 58.8,55.09 57.53,53.82 57.53,45.57 53.72,41.76 53.72,38.58 52.45,37.31 OK4.2
N$12
  Bottom 0.406: R53.1 57.53,57.63 56.26,56.36 56.26,46.2 52.45,42.39 OK4.4
N$13
  Bottom 0.406: R4.1 100.08,47.47 100.71,46.84 100.71,44.93 97.54,41.76 94.36,41.76 93.73,41.12 OK9.6
N$14
  Bottom 0.406: R37.1 100.71,50.01 101.35,49.38 101.35,44.3 98.81,41.76 OK9.4
N$15
  Bottom 0.406: R38.1 101.35,52.55 101.98,51.92 101.98,44.93 103.89,43.03 OK9.2
N$16
  Bottom 0.406: R39.1 101.98,55.09 102.62,54.46 102.62,46.84 107.7,41.76 107.7,37.95 108.33,37.31 108.33,34.14 108.97,33.5 OK3.8
N$17
  Bottom 0.406: R40.1 103.25,57.63 103.89,57 103.89,47.47 108.33,43.03 108.33,40.49 OK3.6
N$18
  Bottom 0.406: R41.1 103.89,60.17 104.52,59.54 104.52,48.11 108.97,43.66 OK3.4
N$19
  Bottom 0.406: R42.1 105.16,62.71 105.79,62.08 105.79,51.92 108.97,48.74 OK3.2
N$20
  Bottom 0.406: R48.1 93.73,44.93 91.82,43.03 89.92,43.03 88.65,41.76 OK9.8
N$21
  Bottom 0.406: R2.1 55.63,77.95 54.99,77.32 54.99,70.33 53.72,69.06 OK8.6
N$22
  Bottom 0.406: R3.1 56.9,75.41 56.26,74.78 56.26,65.89 54.36,63.98 OK8.4
N$23
  Bottom 0.406: OK7.8 53.09,95.73 54.36,94.46 59.44,94.46 R43.1
N$24
  Bottom 0.406: R44.1 62.61,88.11 60.07,90.65 OK7.6
N$25
  Bottom 0.406: OK7.4 R45.1
N$26
  Bottom 0.406: R46.1 54.99,83.03 52.45,80.49 OK7.2
N$27
  Bottom 0.406: R47.1 54.99,80.49 53.72,79.22 53.72,75.41 52.45,74.14 OK8.8
N$28
  Bottom 0.406: R63.1 58.17,72.87 57.53,72.24 57.53,65.89 53.72,62.08 53.72,60.17 52.45,58.9 OK8.2
N$29
  Bottom 0.406: 110.87,86.84 OK2.4 108.97,86.84 108.33,87.48 108.33,90.65 105.79,93.19 R1.1
N$30
  Bottom 0.406: R54.1 107.06,95.73 107.7,95.1 107.7,92.56 108.33,91.92 OK2.2
N$31
  Bottom 0.406: R57.1 106.43,90.65 107.06,90.02 107.06,83.03 108.33,81.76 OK2.6
N$32
  Bottom 0.406: R58.1 105.16,88.11 105.79,87.48 105.79,79.22 108.33,76.68 OK2.8
N$33
  Bottom 0.406: R59.1 103.89,85.57 104.52,84.94 104.52,77.95 107.7,74.78 107.7,70.97 108.33,70.33 OK1.2
N$34
  Bottom 0.406: R60.1 102.62,83.03 103.25,82.4 103.25,77.95 107.06,74.14 107.06,69.7 108.33,68.43 108.33,65.89 108.97,65.25 OK1.4
N$35
  Bottom 0.406: R61.1 101.35,80.49 101.98,79.86 101.98,77.95 106.43,73.51 106.43,69.06 107.7,67.79 107.7,61.44 108.97,60.17 OK1.6
N$36
  Bottom 0.406: R62.1 100.08,77.95 105.16,72.87 105.16,69.06 107.06,67.16 107.06,56.36 108.33,55.09 OK1.8
N$37
  Bottom 0.305: 90.55,62.08 arc180 91.82,63.35
N$39
  Bottom 0.305: 91.82,60.81 arc180 90.55,59.54
N$40
  Bottom 0.305: 90.55,57 arc180 91.82,58.27
N$41
  Bottom 0.305: 103.89,67.16 arc-270 103.89,65.89
  Bottom 0.406: IC6.13 97.54,75.41 101.35,71.6 102.62,71.6 Q1.2 103.89,70.33 103.89,67.16 103.89,66.52 C2.1
N$42
  Bottom 0.406: C3.1 101.35,67.79 98.17,67.79 Q1.1 92.46,70.97 91.82,71.6 91.82,72.24 91.19,72.87 IC6.12
N$43
  Bottom 0.305: 90.55,51.92 arc180 91.82,53.19
N$44
  Bottom 0.305: 99.44,45.57 arc180 98.17,44.3
N$45
  Bottom 0.305: 70.23,88.75 arc180 71.5,87.48
N$46
  Bottom 0.305: 71.5,91.29 arc180 70.23,90.02
N$47
  Bottom 0.305: 90.55,84.94 arc180 91.82,86.21
N$48
  Bottom 0.305: 90.55,88.75 arc-180 91.82,87.48
N$49
  Bottom 0.305: 138.81,65.89 arc-180 140.08,67.16
OA0
  Bottom 0.406: IC4.8 36.58,46.2 39.12,48.74 39.12,51.28 40.39,52.55 OK4.9
OA1
  Bottom 0.406: IC4.7 36.58,43.66 40.39,47.47 OK4.11
OA2
  Bottom 0.406: IC4.6 39.12,41.12 40.39,42.39 OK4.13
OA3
  Bottom 0.406: IC4.5 39.12,38.58 40.39,37.31 OK4.15
OA4
  Bottom 0.406: IC4.4 39.12,36.04 44.2,30.96 53.09,30.96 54.36,32.23 OK5.9
OA5
  Bottom 0.406: IC4.3 40.39,33.5 44.2,29.69 59.44,29.69 60.71,30.96 OK5.11
OA6
  Bottom 0.406: IC4.2 41.66,30.96 44.2,28.42 63.25,28.42 65.79,30.96 OK5.13
OA7
  Bottom 0.406: IC4.1 42.93,28.42 44.2,27.15 67.06,27.15 70.87,30.96 OK5.15
OB0
  Bottom 0.406: OK9.9 88.65,31.6 93.73,26.52 121.03,26.52 122.94,28.42 IC3.8
OB1
  Bottom 0.406: OK9.11 93.73,31.6 97.54,27.79 119.76,27.79 122.94,30.96 IC3.7
OB2
  Bottom 0.406: OK9.13 98.81,31.6 101.35,29.06 118.49,29.06 122.94,33.5 IC3.6
OB3
  Bottom 0.406: OK9.15 103.89,31.6 105.16,30.33 117.86,30.33 123.57,36.04 IC3.5
OB4
  Bottom 0.406: OK3.9 119.13,33.5 124.21,38.58 IC3.4
OB5
  Bottom 0.406: OK3.11 120.4,38.58 122.94,41.12 IC3.3
OB6
  Bottom 0.406: OK3.13 IC3.2
OB7
  Bottom 0.406: OK3.15 120.4,48.74 122.94,46.2 IC3.1
OC0
  Bottom 0.406: OK7.9 39.12,95.73 37.85,94.46 37.85,84.3 36.58,83.03 IC2.8
OC1
  Bottom 0.406: OK7.11 40.39,90.65 39.12,89.38 39.12,81.76 37.85,80.49 IC2.7
OC2
  Bottom 0.406: OK7.13 41.66,85.57 40.39,84.3 40.39,80.49 37.85,77.95 IC2.6
OC3
  Bottom 0.406: OK7.15 37.85,75.41 IC2.5
OC4
  Bottom 0.406: OK8.9 39.12,74.14 37.85,72.87 IC2.4
OC5
  Bottom 0.406: OK8.11 39.12,69.06 37.85,70.33 IC2.3
OC6
  Bottom 0.406: OK8.13 41.66,63.98 37.85,67.79 IC2.2
OC7
  Bottom 0.406: OK8.15 39.12,58.9 37.85,60.17 37.85,63.98 36.58,65.25 IC2.1
OD0
  Bottom 0.406: OK1.9 118.49,55.09 124.21,62.08 124.21,64.62 125.48,66.52 IC1.8
OD1
  Bottom 0.406: OK1.11 118.49,60.17 125.48,69.06 IC1.7
OD2
  Bottom 0.406: OK1.13 119.76,65.25 125.48,71.6 IC1.6
OD3
  Bottom 0.406: OK1.15 121.67,70.33 125.48,74.14 IC1.5
OD4
  Bottom 0.406: OK2.9 IC1.4
OD5
  Bottom 0.406: OK2.11 122.3,81.76 125.48,79.22 IC1.3
OD6
  Bottom 0.406: OK2.13 119.76,86.84 125.48,81.76 IC1.2
OD7
  Bottom 0.406: IC1.1 126.75,84.94 119.76,91.92 OK2.15
VCC
  Bottom 0.254: 83.57,36.68 91.19,36.68 96.27,36.68 101.35,36.68 106.43,36.68
  Bottom 0.305: C1.1 IC6.10 | 143.89,92.56 143.83,92.5 SUPPLY.4
  Bottom 0.406: 93.73,65.25 93.73,55.73 91.82,53.82 87.38,53.82 83.57,50.01 83.57,36.68 83.57,29.69 | 93.73,65.25 R8.2 | 93.73,65.25 C1.1 | OK7.7 48.01,93.19 47.37,92.56 47.37,88.11 | 47.37,39.85 47.37,35.41 48.01,34.77 OK4.1 51.82,34.77 54.36,37.31 58.17,37.31 | 47.37,39.85 47.37,44.93 | 47.37,44.93 47.37,50.01 | 47.37,50.01 47.37,56.36 | 47.37,56.36 47.37,61.44 | 47.37,61.44 47.37,66.52 | 47.37,66.52 47.37,71.6 | 47.37,71.6 47.37,77.95 | 47.37,77.95 47.37,83.03 | 47.37,83.03 47.37,88.11 | 58.17,37.31 63.25,37.31 | 63.25,37.31 68.33,37.31 | 68.33,37.31 72.77,37.31 | 72.77,37.31 73.41,37.95 OK5.1 | 47.37,88.11 OK7.5 | 47.37,83.03 OK7.3 | 47.37,77.95 OK7.1 | 47.37,71.6 OK8.7 | 47.37,66.52 OK8.5 | 47.37,61.44 OK8.3 | 47.37,56.36 OK8.1 | 47.37,50.01 OK4.7 | 47.37,44.93 OK4.5 | 47.37,39.85 OK4.3 | 58.17,37.31 OK5.7 | 63.25,37.31 OK5.5 | 68.33,37.31 OK5.3 | 91.19,36.68 OK9.7 | 96.27,36.68 OK9.5 | 101.35,36.68 OK9.3 | OK9.1 106.43,36.68 107.06,36.68 107.06,33.5 108.33,32.23 111.51,32.23 112.78,33.5 112.78,36.04 | 112.78,41.12 112.78,46.2 | 112.78,46.2 112.78,51.28 | 112.78,51.28 112.78,57.63 | 112.78,57.63 112.78,62.71 | 112.78,62.71 112.78,67.79 | 112.78,67.79 112.78,72.87 | 112.78,72.87 112.78,79.22 | 112.78,79.22 112.78,84.3 | 112.78,84.3 112.78,89.38 | 112.78,89.38 112.78,93.83 | J1.C2 144.53,86.84 143.89,87.48 143.89,92.56 143.89,94.46 142.62,95.73 114.68,95.73 112.78,93.83 | 112.78,46.2 OK3.3 | 112.78,41.12 OK3.5 | 112.78,36.04 112.78,41.12 | 112.78,36.04 OK3.7 | OK2.1 112.14,94.46 112.78,93.83 | 112.78,89.38 OK2.3 | 112.78,84.3 OK2.5 | 112.78,79.22 OK2.7 | 112.78,72.87 OK1.1 | 112.78,67.79 OK1.3 | 112.78,62.71 OK1.5 | 112.78,57.63 OK1.7 | 112.78,51.28 OK3.1 | ISP.6 79.76,32.23 79.76,30.33 80.39,29.69 83.57,29.69
  Bottom 0.406: 83.57,29.69 83.57,25.25 82.93,24.61 77.22,24.61 74.68,27.15 74.68,36.68 74.04,37.31 72.77,37.31
(copper drawn outside any net)
  shapes: Bottom circle x64

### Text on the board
Bottom: Weichen v2.1-22.01.2009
